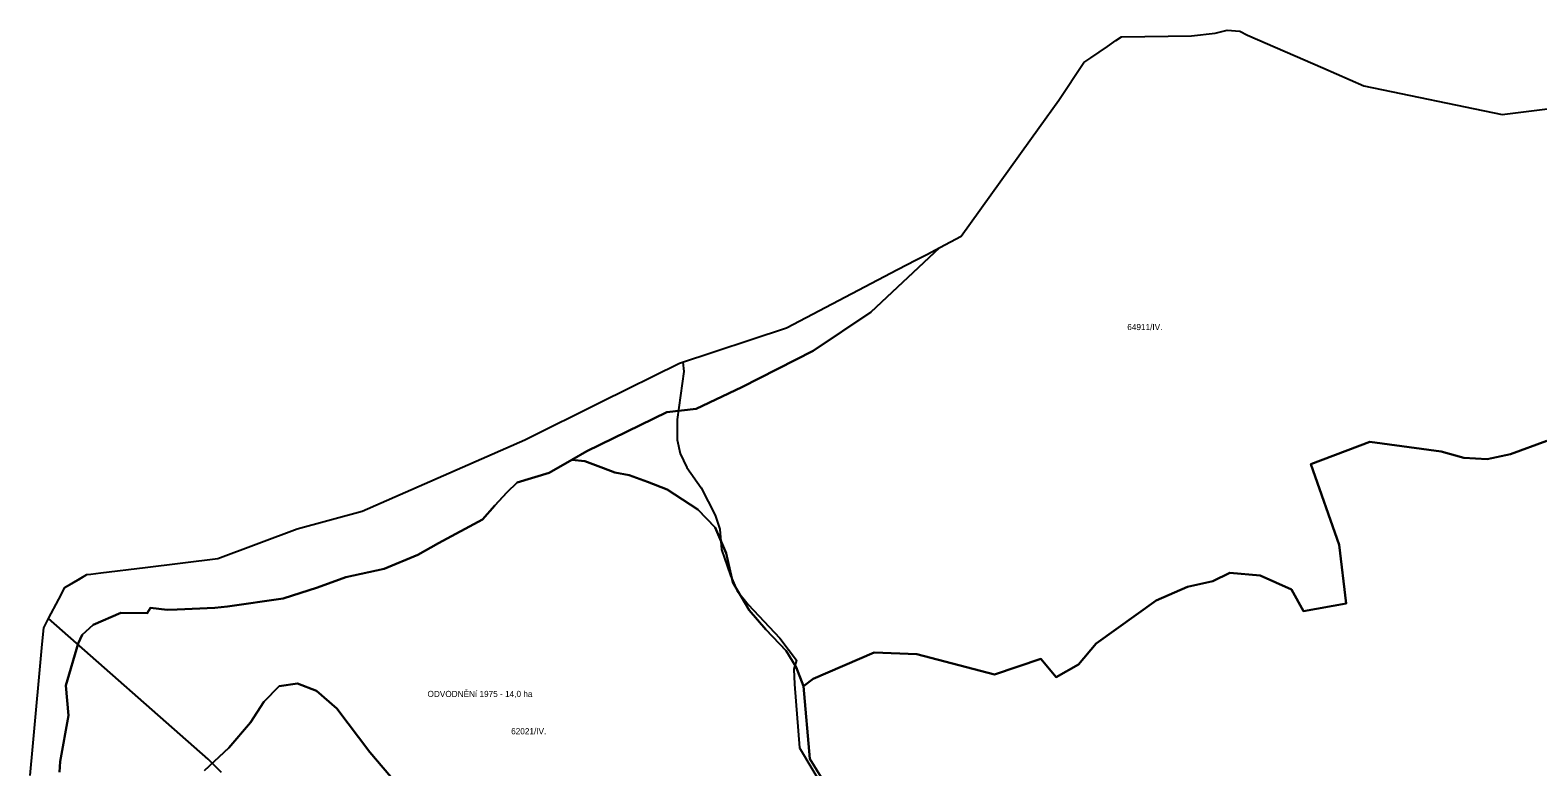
# Model space of a CAD drawing. Extents: x -521621 to -516761, y -1190184 to -1184927.
# Drawn here: x -520795 to -519813, y -1186412 to -1185932 of the extents above; entities that cross this region are included whole.
import ezdxf

# ---------------------------------------------------------------- set-up
doc = ezdxf.new("R2010")
doc.units = 0
doc.layers.add('BPEJ_s', color=7, linetype='Continuous')
doc.layers.add('odvodneni_s', color=7, linetype='Continuous')

msp = doc.modelspace()

# ---------------------------------------------------------------- linework, layer by layer
at = {"layer": 'BPEJ_s'}
for p, q in [((-520202.49, -1186073.69), (-520247.31, -1186115.85)), ((-520229.93, -1186088.15), (-520217.78, -1186081.77)), ((-520217.78, -1186081.77), (-520211.02, -1186078.2)), ((-520211.02, -1186078.2), (-520202.51, -1186073.7)), ((-520202.51, -1186073.7), (-520202.49, -1186073.69)), ((-520302.4, -1186126.16), (-520229.93, -1186088.15)), ((-520247.31, -1186115.85), (-520284.91, -1186141.09)), ((-520372, -1186149.08), (-520302.4, -1186126.16)), ((-520284.91, -1186141.09), (-520331.41, -1186164.81)), ((-520423.09, -1186174.36), (-520372, -1186149.08)), ((-520331.41, -1186164.81), (-520361.18, -1186178.89)), ((-520472.97, -1186199.04), (-520423.09, -1186174.36)), ((-520361.18, -1186178.89), (-520380.43, -1186181.12)), ((-520380.43, -1186181.12), (-520432.58, -1186206.53)), ((-520578.78, -1186245.73), (-520472.97, -1186199.04)), ((-520432.58, -1186206.53), (-520442.17, -1186212.11)), ((-520442.17, -1186212.11), (-520457.05, -1186220.76)), ((-520477.92, -1186227.06), (-520484.58, -1186233.55)), ((-520457.05, -1186220.76), (-520477.92, -1186227.06)), ((-520484.58, -1186233.55), (-520492.49, -1186242.01)), ((-520621.17, -1186257.07), (-520578.78, -1186245.73)), ((-520492.49, -1186242.01), (-520500.41, -1186251.02)), ((-520673, -1186276.47), (-520621.17, -1186257.07)), ((-520500.41, -1186251.02), (-520529.12, -1186266.6)), ((-520529.12, -1186266.6), (-520542.57, -1186274.22)), ((-520720.25, -1186282.28), (-520673, -1186276.47)), ((-520542.57, -1186274.22), (-520564.57, -1186283.33)), ((-520763.58, -1186290.1), (-520758.36, -1186286.97)), ((-520758.36, -1186286.97), (-520755.78, -1186286.65)), ((-520755.78, -1186286.65), (-520749.24, -1186285.85)), ((-520749.24, -1186285.85), (-520720.25, -1186282.28)), ((-520589.57, -1186288.63), (-520608.02, -1186295.37)), ((-520564.57, -1186283.33), (-520589.57, -1186288.63)), ((-520776.5, -1186302.96), (-520772.54, -1186295.47)), ((-520772.54, -1186295.47), (-520763.58, -1186290.1)), ((-520608.02, -1186295.37), (-520630.37, -1186302.64)), ((-520783.24, -1186315.71), (-520776.5, -1186302.96)), ((-520666.67, -1186307.8), (-520674.88, -1186308.57)), ((-520630.37, -1186302.64), (-520666.67, -1186307.8)), ((-520786.41, -1186321.7), (-520783.24, -1186315.71)), ((-520736.2, -1186312.01), (-520754.18, -1186319.77)), ((-520719.02, -1186312.2), (-520736.2, -1186312.01)), ((-520716.73, -1186308.76), (-520719.02, -1186312.2)), ((-520706.03, -1186309.91), (-520716.73, -1186308.76)), ((-520699.34, -1186309.71), (-520706.03, -1186309.91)), ((-520674.88, -1186308.57), (-520699.34, -1186309.71)), ((-520787.38, -1186332.28), (-520786.41, -1186321.7)), ((-520761.43, -1186326.37), (-520763.91, -1186331.99)), ((-520754.18, -1186319.77), (-520761.43, -1186326.37)), ((-520793.49, -1186398.99), (-520787.38, -1186332.28)), ((-520763.91, -1186331.99), (-520771.99, -1186359.39)), ((-520771.99, -1186359.39), (-520770.34, -1186378.88)), ((-520770.34, -1186378.88), (-520775.6, -1186408.89)), ((-520795.23, -1186418.02), (-520793.49, -1186398.99)), ((-520775.6, -1186408.89), (-520776.02, -1186415.82))]:
    msp.add_line(p, q, dxfattribs=at)
for points in [[(-519806.91, -1186199.69), (-519830.49, -1186208.54), (-519845.83, -1186211.69), (-519861.01, -1186210.86), (-519875.77, -1186206.85), (-519922.15, -1186200.52), (-519960.72, -1186215.08), (-519942.18, -1186267.55), (-519937.75, -1186305.74), (-519965.47, -1186310.85), (-519973.27, -1186296.65), (-519993.77, -1186287.64), (-520013.36, -1186285.79), (-520024.6, -1186291.35), (-520041.1, -1186294.91), (-520061.49, -1186303.95), (-520100.56, -1186331.84), (-520112.08, -1186345.71), (-520126.67, -1186353.96), (-520136.73, -1186341.99), (-520166.77, -1186352.07), (-520217.32, -1186338.94), (-520245.21, -1186337.7), (-520285.05, -1186354.89), (-520291.39, -1186359.7), (-520296.08, -1186347.26), (-520302.5, -1186336.61), (-520315.75, -1186322.75), (-520326.79, -1186310.3), (-520337.43, -1186292.22), (-520341.65, -1186272.93), (-520348.87, -1186256.26), (-520360.11, -1186244.61), (-520380.19, -1186231.55), (-520392.84, -1186226.53), (-520404.88, -1186222.11), (-520414.12, -1186220.35), (-520421.56, -1186217.54), (-520433.87, -1186213.04), (-520442.17, -1186212.11), (-520432.58, -1186206.53), (-520380.43, -1186181.12), (-520361.18, -1186178.89), (-520331.41, -1186164.81), (-520284.91, -1186141.09), (-520247.31, -1186115.85), (-520202.49, -1186073.69), (-520188.49, -1186066.29), (-520137.79, -1185995.57), (-520124.89, -1185977.57), (-520108.53, -1185953.17), (-520104.12, -1185950.12), (-520093.21, -1185942.58), (-520087.69, -1185938.77), (-520084.12, -1185936.3), (-520038.5, -1185935.79), (-520023.07, -1185934.04), (-520015.25, -1185932.02), (-520007.02, -1185932.62), (-520002.01, -1185935.24), (-519952.93, -1185956.64), (-519926.25, -1185968.27), (-519835.91, -1185986.97), (-519743.68, -1185975.43)], [(-520270.66, -1186433.76), (-520287.12, -1186407.06), (-520291.39, -1186359.7), (-520285.05, -1186354.89), (-520245.21, -1186337.7), (-520217.32, -1186338.94), (-520166.77, -1186352.07), (-520136.73, -1186341.99), (-520126.67, -1186353.96), (-520112.08, -1186345.71), (-520100.56, -1186331.84), (-520061.49, -1186303.95), (-520041.1, -1186294.91), (-520024.6, -1186291.35), (-520013.36, -1186285.79), (-519993.77, -1186287.64), (-519973.27, -1186296.65), (-519965.47, -1186310.85), (-519937.75, -1186305.74), (-519942.18, -1186267.55), (-519960.72, -1186215.08), (-519922.15, -1186200.52), (-519875.77, -1186206.85), (-519861.01, -1186210.86), (-519845.83, -1186211.69), (-519830.49, -1186208.54), (-519806.91, -1186199.69)], [(-520776.02, -1186415.82), (-520775.6, -1186408.89), (-520770.34, -1186378.88), (-520771.99, -1186359.39), (-520763.91, -1186331.99), (-520761.43, -1186326.37), (-520754.18, -1186319.77), (-520736.2, -1186312.01), (-520719.02, -1186312.2), (-520716.73, -1186308.76), (-520706.03, -1186309.91), (-520699.34, -1186309.71), (-520674.88, -1186308.57), (-520666.67, -1186307.8), (-520630.37, -1186302.64), (-520608.02, -1186295.37), (-520589.57, -1186288.63), (-520564.57, -1186283.33), (-520542.57, -1186274.22), (-520529.12, -1186266.6), (-520500.41, -1186251.02), (-520492.49, -1186242.01), (-520484.58, -1186233.55), (-520477.92, -1186227.06), (-520457.05, -1186220.76), (-520442.17, -1186212.11), (-520433.87, -1186213.04), (-520421.56, -1186217.54), (-520414.12, -1186220.35), (-520404.88, -1186222.11), (-520392.84, -1186226.53), (-520380.19, -1186231.55), (-520360.11, -1186244.61), (-520348.87, -1186256.26), (-520341.65, -1186272.93), (-520337.43, -1186292.22), (-520326.79, -1186310.3), (-520315.75, -1186322.75), (-520302.5, -1186336.61), (-520296.08, -1186347.26), (-520291.39, -1186359.7), (-520287.12, -1186407.06), (-520270.66, -1186433.76)], [(-520681.69, -1186414.67), (-520665.76, -1186399.98), (-520651.71, -1186383.42), (-520642.96, -1186369.98), (-520632.97, -1186359.67), (-520621.1, -1186358.1), (-520608.61, -1186362.79), (-520595.49, -1186374.35), (-520573.94, -1186402.79), (-520551.45, -1186429.05)], [(-520551.45, -1186429.05), (-520573.94, -1186402.79), (-520595.49, -1186374.35), (-520608.61, -1186362.79), (-520621.1, -1186358.1), (-520632.97, -1186359.67), (-520642.96, -1186369.98), (-520651.71, -1186383.42), (-520665.76, -1186399.98), (-520681.69, -1186414.67)]]:
    msp.add_lwpolyline(points, dxfattribs=at)
at = {"layer": 'odvodneni_s'}
msp.add_lwpolyline([(-520670.64, -1186416.07), (-520679.29, -1186407.25), (-520783.24, -1186315.71), (-520776.5, -1186302.96), (-520772.54, -1186295.47), (-520758.36, -1186286.97), (-520755.78, -1186286.65), (-520749.24, -1186285.85), (-520720.25, -1186282.28), (-520673, -1186276.47), (-520621.17, -1186257.07), (-520578.78, -1186245.73), (-520472.97, -1186199.04), (-520423.09, -1186174.36), (-520372, -1186149.08), (-520369.95, -1186148.41), (-520369.19, -1186154.53), (-520373.65, -1186185.81), (-520373.51, -1186199.21), (-520371.56, -1186208.15), (-520367.37, -1186217.08), (-520357.88, -1186230.49), (-520348.8, -1186248.36), (-520345.87, -1186257.3), (-520344.75, -1186270.7), (-520338.89, -1186287.59), (-520334.56, -1186297.51), (-520327.44, -1186306.58), (-520306.78, -1186328.36), (-520295.88, -1186342.88), (-520297.59, -1186348.69), (-520297.17, -1186358.49), (-520293.78, -1186399.85), (-520276.48, -1186429.13)], dxfattribs=at)

# ---------------------------------------------------------------- texts
at = {"layer": 'BPEJ_s'}
for s, p in [('64911/IV.', (-520080.28, -1186127.59)), ('62021/IV.', (-520481.79, -1186391.11))]:
    msp.add_text(s, height=4, dxfattribs=at).set_placement(p)
at = {"layer": 'odvodneni_s'}
msp.add_text('ODVODNĚNí 1975 - 14,0 ha', height=4, dxfattribs=at).set_placement((-520536.29, -1186366.8))

doc.saveas('drawing.dxf')
